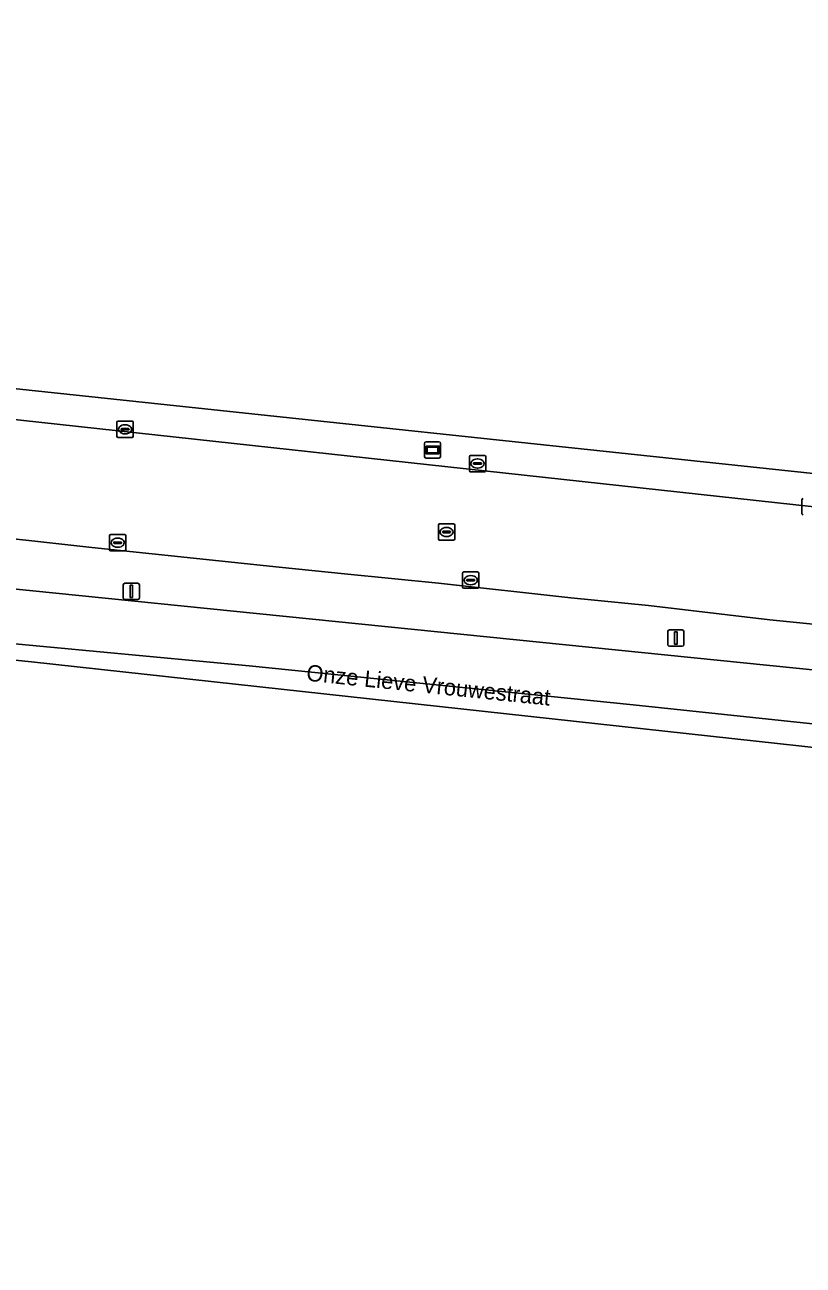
# Model space of a CAD drawing. Extents: x 161758 to 162722, y 384793 to 385405.
# Drawn here: x 162200.5 to 162248.2, y 384798.9 to 384875 of the extents above; entities that cross this region are included whole.
import ezdxf

# ---------------------------------------------------------------- set-up
doc = ezdxf.new("R2010")
doc.units = 0
for name, color, linetype in [('IMGEO_Berm_groen', 7, 'Continuous'), ('IMGEO_Groenvoorziening', 7, 'Continuous'), ('IMGEO_Kolk', 7, 'Continuous'), ('IMGEO_Lichtmast', 7, 'Continuous'), ('IMGEO_Openbare_ruimte_label', 7, 'Continuous'), ('IMGEO_Rijbaan_lokaal_open', 7, 'Continuous'), ('IMGEO_Rijbaan_regionaal_gesloten', 7, 'Continuous'), ('IMGEO_Rioolput', 7, 'Continuous'), ('IMGEO_Verkeersbordpaal', 7, 'Continuous'), ('IMGEO_Voetpad_open', 7, 'Continuous'), ('IMGEO_Wegwijzer', 7, 'Continuous')]:
    doc.layers.add(name, color=color, linetype=linetype)

msp = doc.modelspace()

# ---------------------------------------------------------------- linework, layer by layer
at = {"layer": 'IMGEO_Berm_groen'}
for points in [[(162196.294, 384843.825), (162176.537, 384845.917), (162169.888, 384846.605), (162156.076, 384848.057), (162140.223, 384849.851), (162121.361, 384851.862), (162121.052, 384848.339), (162185.929, 384841.772), (162187.436, 384841.619), (162189.251, 384841.435), (162192.767, 384841.08), (162194.3, 384840.925), (162196.141, 384840.739), (162261.713, 384834.101), (162291.726, 384830.473), (162298.135, 384829.505), (162306.89, 384828.091), (162315.827, 384826.441), (162321.473, 384825.346), (162350.99, 384818.894), (162380.078, 384810.862), (162402.695, 384803.51), (162404.257, 384805.879)], [(162266.874, 384836.344), (162253.954, 384837.702), (162246.186, 384838.478), (162238.742, 384839.348), (162233.995, 384839.83), (162225.879, 384840.718), (162220.098, 384841.298), (162216.103, 384841.703), (162204.623, 384842.922), (162196.294, 384843.825)]]:
    msp.add_lwpolyline(points, dxfattribs=at)
at = {"layer": 'IMGEO_Groenvoorziening'}
msp.add_lwpolyline([(162199.818, 384852.651), (162250.191, 384847.307), (162250.063, 384854.438), (162250.266, 384858.579), (162250.523, 384863.018), (162251.237, 384867.101), (162251.395, 384869.434), (162252.229, 384882.814)], dxfattribs=at)
at = {"layer": 'IMGEO_Kolk'}
for p, q in [((162206.154, 384849.734), (162206.154, 384850.586)), ((162206.229, 384850.66), (162207.081, 384850.66)), ((162206.413, 384850.154), (162206.413, 384850.166)), ((162206.851, 384850.117), (162206.453, 384850.117)), ((162206.456, 384850.203), (162206.854, 384850.203)), ((162206.642, 384850.44), (162206.667, 384850.44)), ((162206.897, 384850.166), (162206.897, 384850.154)), ((162207.155, 384850.586), (162207.155, 384849.734)), ((162207.081, 384849.66), (162206.229, 384849.66)), ((162206.665, 384849.88), (162206.64, 384849.88)), ((162227.764, 384847.634), (162227.764, 384848.486)), ((162227.839, 384848.56), (162228.691, 384848.56)), ((162228.765, 384848.486), (162228.765, 384847.634)), ((162228.023, 384848.054), (162228.023, 384848.066)), ((162228.461, 384848.017), (162228.063, 384848.017)), ((162228.066, 384848.103), (162228.464, 384848.103)), ((162228.275, 384847.78), (162228.25, 384847.78)), ((162228.252, 384848.34), (162228.277, 384848.34)), ((162228.507, 384848.066), (162228.507, 384848.054)), ((162228.691, 384847.56), (162227.839, 384847.56)), ((162248.159, 384844.984), (162248.159, 384845.836)), ((162205.698, 384842.781), (162205.698, 384843.633)), ((162205.773, 384843.707), (162206.625, 384843.707)), ((162205.957, 384843.201), (162205.957, 384843.213)), ((162206.395, 384843.164), (162205.997, 384843.164)), ((162206, 384843.25), (162206.398, 384843.25)), ((162206.186, 384843.487), (162206.211, 384843.487)), ((162206.441, 384843.213), (162206.441, 384843.201)), ((162206.699, 384843.633), (162206.699, 384842.781)), ((162206.625, 384842.707), (162205.773, 384842.707)), ((162206.209, 384842.927), (162206.184, 384842.927)), ((162227.345, 384840.486), (162227.345, 384841.338)), ((162227.42, 384841.412), (162228.272, 384841.412)), ((162227.604, 384840.906), (162227.604, 384840.918)), ((162228.042, 384840.869), (162227.644, 384840.869)), ((162227.647, 384840.955), (162228.045, 384840.955)), ((162227.833, 384841.192), (162227.858, 384841.192)), ((162228.088, 384840.918), (162228.088, 384840.906)), ((162228.346, 384841.338), (162228.346, 384840.486)), ((162228.272, 384840.412), (162227.42, 384840.412)), ((162227.856, 384840.632), (162227.831, 384840.632))]:
    msp.add_line(p, q, dxfattribs=at)
for points in [[(162206.154, 384849.734), (162206.154, 384850.586)], [(162206.229, 384850.66), (162207.081, 384850.66)], [(162207.155, 384850.586), (162207.155, 384849.734)], [(162207.081, 384849.66), (162206.229, 384849.66)], [(162227.764, 384847.634), (162227.764, 384848.486)], [(162227.839, 384848.56), (162228.691, 384848.56)], [(162228.765, 384848.486), (162228.765, 384847.634)], [(162228.691, 384847.56), (162227.839, 384847.56)], [(162248.159, 384844.984), (162248.159, 384845.836)], [(162205.698, 384842.781), (162205.698, 384843.633)], [(162205.773, 384843.707), (162206.625, 384843.707)], [(162206.699, 384843.633), (162206.699, 384842.781)], [(162206.625, 384842.707), (162205.773, 384842.707)], [(162227.345, 384840.486), (162227.345, 384841.338)], [(162227.42, 384841.412), (162228.272, 384841.412)], [(162228.346, 384841.338), (162228.346, 384840.486)], [(162228.272, 384840.412), (162227.42, 384840.412)]]:
    msp.add_lwpolyline(points, dxfattribs=at)
for centre, radius, start, end in [((162206.231, 384850.584), 0.0765, 91.55205, 178.44795), ((162206.231, 384850.584), 0.0765, 91.55205, 178.44795), ((162206.453, 384850.163), 0.0403, 85.87752, 175.75265), ((162206.45, 384850.153), 0.0366, 178.93798, 274.71019), ((162206.854, 384850.16), 0.043, 264.86636, 352.45326), ((162206.858, 384850.165), 0.0386, 1.73085, 96.63898), ((162207.079, 384850.584), 0.0765, 1.55205, 88.44795), ((162207.079, 384850.584), 0.0765, 1.55205, 88.44795), ((162206.231, 384849.736), 0.0765, 181.55205, 268.44795), ((162206.231, 384849.736), 0.0765, 181.55205, 268.44795), ((162207.079, 384849.736), 0.0765, 271.55205, 358.44795), ((162207.079, 384849.736), 0.0765, 271.55205, 358.44795), ((162227.841, 384848.484), 0.0765, 91.55205, 178.44795), ((162227.841, 384848.484), 0.0765, 91.55205, 178.44795), ((162228.689, 384848.484), 0.0765, 1.55205, 88.44795), ((162228.689, 384848.484), 0.0765, 1.55205, 88.44795), ((162228.063, 384848.063), 0.0403, 85.87752, 175.75265), ((162228.06, 384848.053), 0.0366, 178.93798, 274.71019), ((162228.464, 384848.06), 0.043, 264.86636, 352.45326), ((162228.468, 384848.065), 0.0386, 1.73085, 96.63898), ((162227.841, 384847.636), 0.0765, 181.55205, 268.44795), ((162227.841, 384847.636), 0.0765, 181.55205, 268.44795), ((162228.689, 384847.636), 0.0765, 271.55205, 358.44795), ((162228.689, 384847.636), 0.0765, 271.55205, 358.44795), ((162248.236, 384845.834), 0.0765, 91.55205, 178.44795), ((162248.236, 384845.834), 0.0765, 91.55205, 178.44795), ((162248.236, 384844.986), 0.0765, 181.55205, 268.44795), ((162248.236, 384844.986), 0.0765, 181.55205, 268.44795), ((162205.775, 384843.631), 0.0765, 91.55205, 178.44795), ((162205.775, 384843.631), 0.0765, 91.55205, 178.44795), ((162205.997, 384843.21), 0.0403, 85.87752, 175.75265), ((162205.994, 384843.2), 0.0366, 178.93798, 274.71019), ((162206.398, 384843.207), 0.043, 264.86636, 352.45326), ((162206.402, 384843.212), 0.0386, 1.73085, 96.63898), ((162206.623, 384843.631), 0.0765, 1.55205, 88.44795), ((162206.623, 384843.631), 0.0765, 1.55205, 88.44795), ((162205.775, 384842.783), 0.0765, 181.55205, 268.44795), ((162205.775, 384842.783), 0.0765, 181.55205, 268.44795), ((162206.623, 384842.783), 0.0765, 271.55205, 358.44795), ((162206.623, 384842.783), 0.0765, 271.55205, 358.44795), ((162227.422, 384841.336), 0.0765, 91.55205, 178.44795), ((162227.422, 384841.336), 0.0765, 91.55205, 178.44795), ((162227.644, 384840.915), 0.0403, 85.87752, 175.75265), ((162227.641, 384840.905), 0.0366, 178.93798, 274.71019), ((162228.045, 384840.912), 0.043, 264.86636, 352.45326), ((162228.049, 384840.917), 0.0386, 1.73085, 96.63898), ((162228.27, 384841.336), 0.0765, 1.55205, 88.44795), ((162228.27, 384841.336), 0.0765, 1.55205, 88.44795), ((162227.422, 384840.488), 0.0765, 181.55205, 268.44795), ((162227.422, 384840.488), 0.0765, 181.55205, 268.44795), ((162228.27, 384840.488), 0.0765, 271.55205, 358.44795), ((162228.27, 384840.488), 0.0765, 271.55205, 358.44795)]:
    msp.add_arc(centre, radius, start, end, dxfattribs=at)
for centre, major_axis, ratio, start_param, end_param in [((162206.641, 384850.16), (-0.387, 0.002), 0.722429, 4.712389, 7.853982), ((162206.666, 384850.16), (-0.39, 0.002), 0.717154, 1.570796, 4.712389), ((162228.251, 384848.06), (-0.387, 0.002), 0.722429, 4.712389, 7.853982), ((162228.276, 384848.06), (-0.39, 0.002), 0.717154, 1.570796, 4.712389), ((162206.185, 384843.207), (-0.387, 0.002), 0.722429, 4.712389, 7.853982), ((162206.21, 384843.207), (-0.39, 0.002), 0.717154, 1.570796, 4.712389), ((162227.832, 384840.912), (-0.387, 0.002), 0.722429, 4.712389, 7.853982), ((162227.857, 384840.912), (-0.39, 0.002), 0.717154, 1.570796, 4.712389)]:
    msp.add_ellipse(centre, major_axis=major_axis, ratio=ratio, start_param=start_param, end_param=end_param, dxfattribs=at)
at = {"layer": 'IMGEO_Lichtmast'}
for p, q in [((162206.537, 384839.825), (162206.537, 384840.625)), ((162206.537, 384840.625), (162206.537, 384839.825)), ((162206.637, 384840.725), (162207.427, 384840.725)), ((162207.427, 384840.725), (162206.637, 384840.725)), ((162207.527, 384840.625), (162207.527, 384839.825)), ((162207.527, 384839.825), (162207.527, 384840.625)), ((162207.427, 384839.725), (162206.637, 384839.725)), ((162206.637, 384839.725), (162207.427, 384839.725))]:
    msp.add_line(p, q, dxfattribs=at)
msp.add_lwpolyline([(162206.957, 384840.6), (162207.107, 384840.6), (162207.107, 384839.85), (162206.957, 384839.85), (162206.957, 384840.6)], dxfattribs=at)
for centre, start, end in [((162206.637, 384840.625), 90, 180), ((162206.637, 384840.625), 90, 180), ((162207.427, 384840.625), 0, 90), ((162207.427, 384840.625), 360, 90), ((162206.637, 384839.825), 180, 270), ((162206.637, 384839.825), 180, 270), ((162207.427, 384839.825), 270, 0), ((162207.427, 384839.825), 270, 0)]:
    msp.add_arc(centre, 0.1, start, end, dxfattribs=at)
at = {"layer": 'IMGEO_Rijbaan_lokaal_open'}
for points in [[(162065.033, 384857.642), (162072.258, 384856.957), (162097.628, 384854.37), (162105.852, 384853.479), (162103.299, 384850.228), (162108.896, 384849.572), (162109.342, 384850.113), (162114.246, 384852.545), (162120.024, 384851.99), (162121.361, 384851.862), (162140.223, 384849.851), (162156.076, 384848.057), (162169.888, 384846.605), (162176.537, 384845.917), (162196.294, 384843.825), (162204.623, 384842.922), (162216.103, 384841.703), (162220.098, 384841.298), (162225.879, 384840.718), (162233.995, 384839.83), (162238.742, 384839.348), (162246.186, 384838.478), (162253.954, 384837.702), (162266.874, 384836.344)], [(162336.349, 384832.447), (162327.195, 384834.339), (162316.831, 384836.287), (162288.799, 384840.797), (162274.417, 384842.694), (162259.864, 384844.251), (162248.91, 384845.406), (162196.657, 384851.104)]]:
    msp.add_lwpolyline(points, dxfattribs=at)
at = {"layer": 'IMGEO_Rijbaan_regionaal_gesloten'}
for points in [[(162108.003, 384845.421), (162200.922, 384835.899), (162293.884, 384825.735), (162372.87, 384808.275), (162399.667, 384798.916)], [(162350.99, 384818.894), (162321.473, 384825.346), (162315.827, 384826.441), (162306.89, 384828.091), (162298.135, 384829.505), (162291.726, 384830.473), (162261.713, 384834.101), (162196.141, 384840.739)], [(162195.974, 384837.38), (162214.263, 384835.667), (162237.809, 384833.267), (162257.705, 384831.166), (162270.053, 384829.916), (162282.25, 384828.516), (162293.698, 384826.815), (162308.096, 384824.465), (162319.694, 384822.315), (162339.29, 384818.314), (162351.687, 384815.264)], [(162399.667, 384798.916), (162400.805, 384800.643), (162391.579, 384803.612), (162377.182, 384808.313), (162372.661, 384809.573), (162364.985, 384811.713), (162351.687, 384815.264), (162339.29, 384818.314), (162319.694, 384822.315), (162308.096, 384824.465), (162293.698, 384826.815), (162282.25, 384828.516), (162270.053, 384829.916), (162257.705, 384831.166), (162237.809, 384833.267), (162214.263, 384835.667), (162195.974, 384837.38)]]:
    msp.add_lwpolyline(points, dxfattribs=at)
at = {"layer": 'IMGEO_Rioolput'}
for p, q in [((162225.867, 384843.436), (162225.867, 384844.288)), ((162225.942, 384844.362), (162226.794, 384844.362)), ((162226.126, 384843.856), (162226.126, 384843.868)), ((162226.169, 384843.905), (162226.567, 384843.905)), ((162226.355, 384844.142), (162226.38, 384844.142)), ((162226.61, 384843.868), (162226.61, 384843.856)), ((162226.868, 384844.288), (162226.868, 384843.436)), ((162226.794, 384843.362), (162225.942, 384843.362)), ((162226.564, 384843.819), (162226.166, 384843.819)), ((162226.378, 384843.582), (162226.353, 384843.582))]:
    msp.add_line(p, q, dxfattribs=at)
for points in [[(162225.867, 384843.436), (162225.867, 384844.288)], [(162225.942, 384844.362), (162226.794, 384844.362)], [(162226.868, 384844.288), (162226.868, 384843.436)], [(162226.794, 384843.362), (162225.942, 384843.362)]]:
    msp.add_lwpolyline(points, dxfattribs=at)
for centre, radius, start, end in [((162225.944, 384844.286), 0.0765, 91.55205, 178.44795), ((162225.944, 384844.286), 0.0765, 91.55205, 178.44795), ((162226.166, 384843.865), 0.0403, 85.87752, 175.75265), ((162226.571, 384843.867), 0.0386, 1.73085, 96.63898), ((162226.792, 384844.286), 0.0765, 1.55205, 88.44795), ((162226.792, 384844.286), 0.0765, 1.55205, 88.44795), ((162225.944, 384843.438), 0.0765, 181.55205, 268.44795), ((162225.944, 384843.438), 0.0765, 181.55205, 268.44795), ((162226.163, 384843.855), 0.0366, 178.93798, 274.71019), ((162226.567, 384843.862), 0.043, 264.86636, 352.45326), ((162226.792, 384843.438), 0.0765, 271.55205, 358.44795), ((162226.792, 384843.438), 0.0765, 271.55205, 358.44795)]:
    msp.add_arc(centre, radius, start, end, dxfattribs=at)
for centre, major_axis, ratio, start_param, end_param in [((162226.354, 384843.862), (-0.387, 0.002), 0.722429, 4.712389, 7.853982), ((162226.379, 384843.862), (-0.39, 0.002), 0.717154, 1.570796, 4.712389)]:
    msp.add_ellipse(centre, major_axis=major_axis, ratio=ratio, start_param=start_param, end_param=end_param, dxfattribs=at)
at = {"layer": 'IMGEO_Verkeersbordpaal'}
for p, q in [((162240.031, 384837.858), (162240.821, 384837.858)), ((162240.821, 384837.858), (162240.031, 384837.858)), ((162239.931, 384836.958), (162239.931, 384837.758)), ((162239.931, 384837.758), (162239.931, 384836.958)), ((162240.921, 384837.758), (162240.921, 384836.958)), ((162240.921, 384836.958), (162240.921, 384837.758)), ((162240.821, 384836.858), (162240.031, 384836.858)), ((162240.031, 384836.858), (162240.821, 384836.858))]:
    msp.add_line(p, q, dxfattribs=at)
msp.add_lwpolyline([(162240.351, 384837.733), (162240.501, 384837.733), (162240.501, 384836.983), (162240.351, 384836.983), (162240.351, 384837.733)], dxfattribs=at)
for centre, start, end in [((162240.031, 384837.758), 90, 180), ((162240.031, 384837.758), 90, 180), ((162240.821, 384837.758), 0, 90), ((162240.821, 384837.758), 360, 90), ((162240.031, 384836.958), 180, 270), ((162240.031, 384836.958), 180, 270), ((162240.821, 384836.958), 270, 0), ((162240.821, 384836.958), 270, 0)]:
    msp.add_arc(centre, 0.1, start, end, dxfattribs=at)
at = {"layer": 'IMGEO_Voetpad_open'}
for points in [[(162132.687, 384857.788), (162145.258, 384856.454), (162172.558, 384853.51), (162173.734, 384853.372), (162179.371, 384852.762), (162180.669, 384852.613), (162186.438, 384852.069), (162189.662, 384851.764), (162193.185, 384851.432), (162196.657, 384851.104), (162248.91, 384845.406), (162248.991, 384846.134), (162260.001, 384844.996), (162259.864, 384844.251), (162274.417, 384842.694), (162288.799, 384840.797), (162316.831, 384836.287), (162327.195, 384834.339), (162336.349, 384832.447)], [(162408.323, 384812.045), (162409.676, 384814.097), (162394.807, 384818.82), (162368.573, 384826.736), (162355.529, 384830.108), (162344.315, 384832.787), (162342.336, 384833.244), (162322.861, 384837.358), (162275.019, 384844.76), (162259.423, 384846.371), (162257.607, 384846.559), (162257.064, 384846.615), (162250.932, 384847.228), (162250.191, 384847.307), (162199.818, 384852.651)]]:
    msp.add_lwpolyline(points, dxfattribs=at)
at = {"layer": 'IMGEO_Wegwijzer'}
for p, q in [((162225.01, 384848.493), (162225.01, 384849.293)), ((162225.01, 384849.293), (162225.01, 384848.493)), ((162225.11, 384849.393), (162225.9, 384849.393)), ((162225.9, 384849.393), (162225.11, 384849.393)), ((162226, 384849.293), (162226, 384848.493)), ((162226, 384848.493), (162226, 384849.293)), ((162225.9, 384848.393), (162225.11, 384848.393)), ((162225.11, 384848.393), (162225.9, 384848.393))]:
    msp.add_line(p, q, dxfattribs=at)
for points in [[(162225.111, 384849.125), (162225.899, 384849.125), (162225.899, 384848.661), (162225.111, 384848.661), (162225.111, 384849.125)], [(162225.176, 384849.06), (162225.176, 384848.726), (162225.834, 384848.726), (162225.834, 384849.06), (162225.176, 384849.06)]]:
    msp.add_lwpolyline(points, dxfattribs=at)
for centre, start, end in [((162225.11, 384849.293), 90, 180), ((162225.11, 384849.293), 90, 180), ((162225.9, 384849.293), 0, 90), ((162225.9, 384849.293), 360, 90), ((162225.11, 384848.493), 180, 270), ((162225.11, 384848.493), 180, 270), ((162225.9, 384848.493), 270, 0), ((162225.9, 384848.493), 270, 0)]:
    msp.add_arc(centre, 0.1, start, end, dxfattribs=at)

# ---------------------------------------------------------------- texts
at = {"layer": 'IMGEO_Openbare_ruimte_label'}
msp.add_text('Onze Lieve Vrouwestraat', height=1, rotation=354.14691, dxfattribs=at).set_placement((162217.735, 384834.751))

doc.saveas('drawing.dxf')
